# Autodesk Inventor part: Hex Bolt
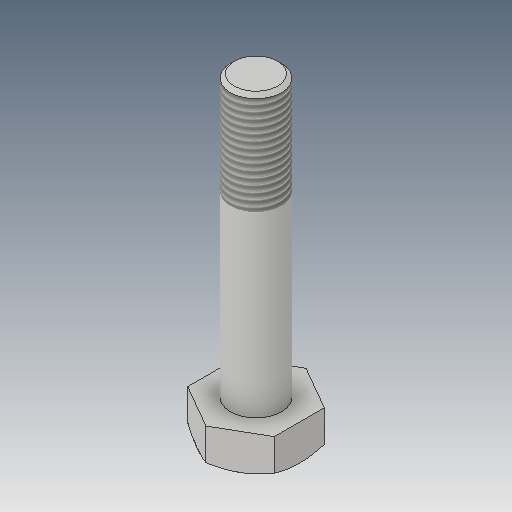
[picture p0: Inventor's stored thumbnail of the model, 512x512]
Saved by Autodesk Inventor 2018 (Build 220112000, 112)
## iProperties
Created: 2016-05
Part Number: Hex Bolt
Material: Generic
Document SubType Name: Modeling
Designer: CADCIM
Density: 1 g/cm^3
Appearance: Default
Author: CADCIM
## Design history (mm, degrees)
sketch "Sketch1"
  geometry: L1 (0, -19.63)-(-17, -9.815); L2 (-17, -9.815)-(-17, 9.815); L3 (-17, 9.815)-(0, 19.63); L4 (0, 19.63)-(17, 9.815); L5 (17, 9.815)-(17, -9.815); L6 (17, -9.815)-(0, -19.63); 2 further points
  constraints: 12 end point, 1 coincident, 13 other
  dimensions: "d0" = 34 distance between parallel lines of L2 L5
extrude "Extrusion1" new body sketch "Sketch1" distance "d1" = 14; taper "d2" = 0 deg
sketch "Sketch2"
  geometry: 1 further point
sketch "Sketch3"
  geometry: C1 r 10 at (0, 0); 1 further point
  constraints: 1 centre point, 1 coincident
  dimensions: "d3" = 20 diameter of C1
extrude "Extrusion2" join sketch "Sketch3" distance "d4" = 110; taper "d5" = 0 deg
thread "Thread1" dims "d6" = 40, "d7" = 0
sketch "Sketch4"
  geometry: L1 (0, -19.63)-(17, -9.815) reference; C1 r 17 at (0, 0); 1 further point
  constraints: 1 centre point, 1 coincident, 1 tangent
extrude "Extrusion3" sketch "Sketch4" distance "d8" = 200; taper "d9" = 60 deg
chamfer "Chamfer1" distance "d10" = 1.5; stored, may be unused: second distance "d11" = 2, angle "d12" = 45 deg
body "Solid1"
